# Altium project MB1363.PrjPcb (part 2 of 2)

## Sheet MCU_144_POWER.SchDoc: MCU 144 POWER
size A4; Date: Not used; ApprovedBy: Not used; CheckedBy: Not used; Author: Not used; CompanyName: STMicroelectronics; DrawnBy: Not used; Engineer: Not used; Organization: Not used; Address1: Not used; Address2: Not used; Address3: Not used; Address4: Not used; DocumentNumber: 4; Revision: Not used; SheetNumber: 4; SheetTotal: 9
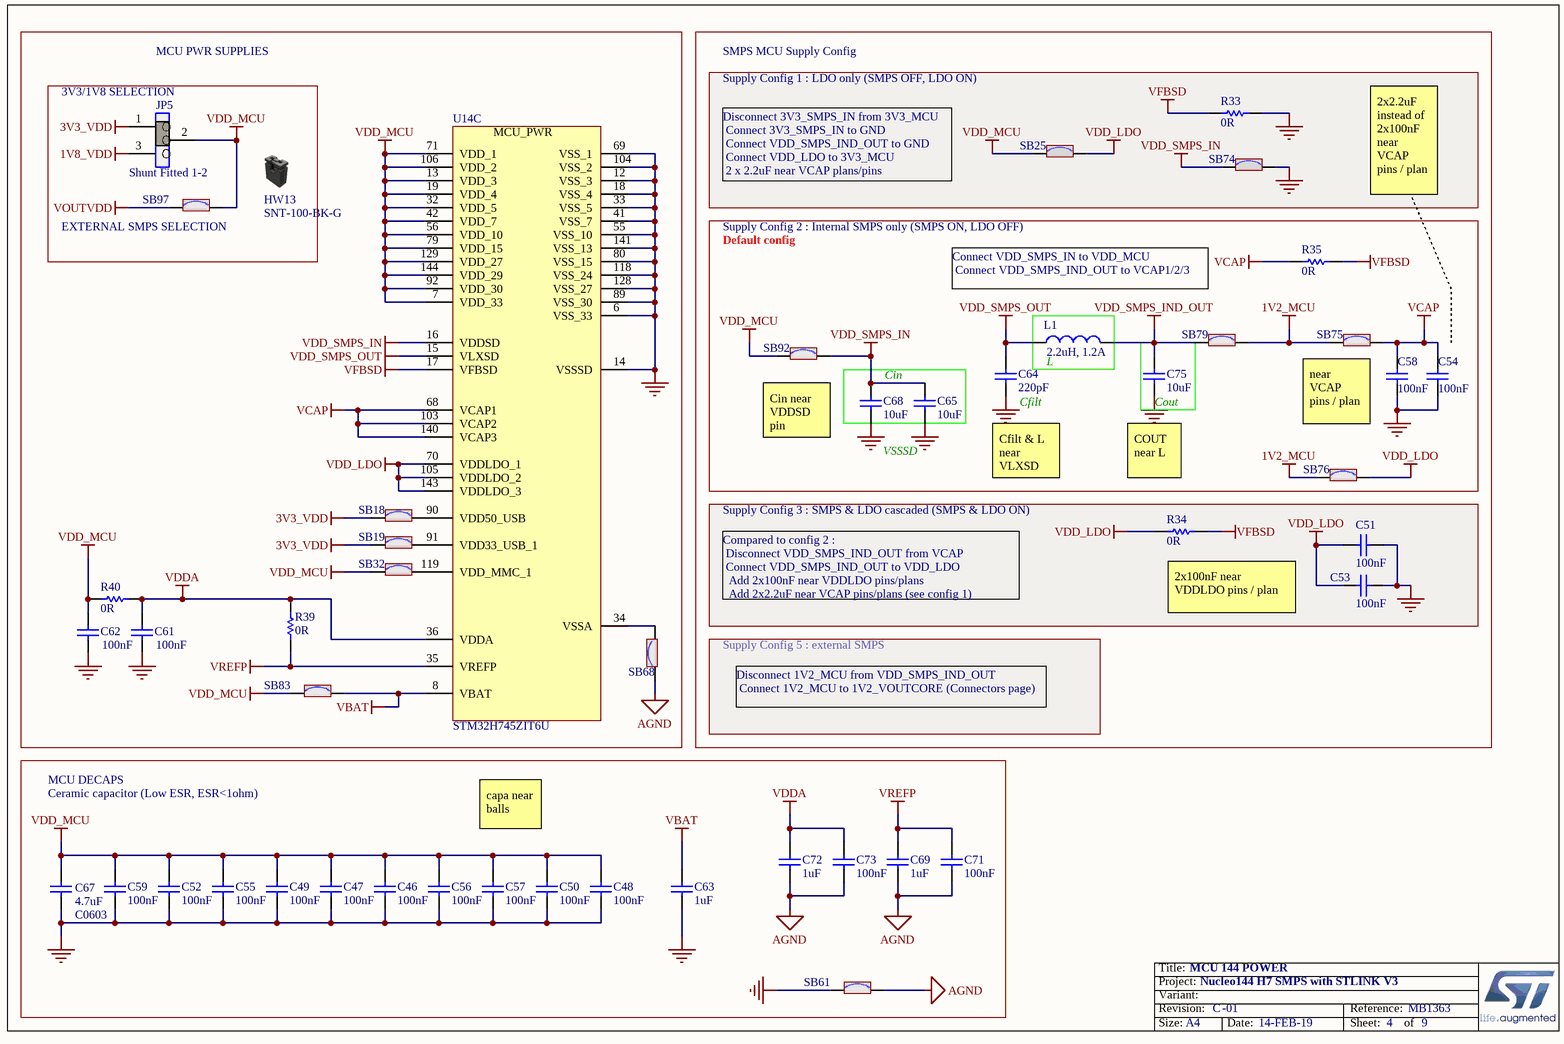
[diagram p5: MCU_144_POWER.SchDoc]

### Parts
C46  value 100nF  [C0402]  (hidden comment: Capacitor)
C47  value 100nF  [C0402]  (hidden comment: Capacitor)
C48  value 100nF  [C0402]  (hidden comment: Capacitor)
C49  value 100nF  [C0402]  (hidden comment: Capacitor)
C50  value 100nF  [C0402]  (hidden comment: Capacitor)
C51  value 100nF  [C0402]  (hidden comment: Capacitor)
C52  value 100nF  [C0402]  (hidden comment: Capacitor)
C53  value 100nF  [C0402]  (hidden comment: Capacitor)
C54  value 100nF  [C0402]  (hidden comment: Capacitor)
C55  value 100nF  [C0402]  (hidden comment: Capacitor)
C56  value 100nF  [C0402]  (hidden comment: Capacitor)
C57  value 100nF  [C0402]  (hidden comment: Capacitor)
C58  value 100nF  [C0402]  (hidden comment: Capacitor)
C59  value 100nF  [C0402]  (hidden comment: Capacitor)
C61  value 100nF  [C0402]  (hidden comment: Capacitor)
C62  value 100nF  [C0402]  (hidden comment: Capacitor)
C63  value 1uF  [C0603]  (hidden comment: Capacitor)
C64  value 220pF  [C0402]  (hidden comment: Capacitor)
C65  value 10uF  [C0402]  (hidden comment: Capacitor)
C67  value 4.7uF  [C0603]  (hidden comment: Capacitor)
C68  value 10uF  [C0402]  (hidden comment: Capacitor)
C69  value 1uF  [C0603]  (hidden comment: Capacitor)
C71  value 100nF  [C0402]  (hidden comment: Capacitor)
C72  value 1uF  [C0603]  (hidden comment: Capacitor)
C73  value 100nF  [C0402]  (hidden comment: Capacitor)
C75  value 10uF  [C0603]  (hidden comment: Capacitor)
HW13  value SNT-100-BK-G  (hidden comment: Shunt Black 2.54mm)  (mechanical)
JP5  value Shunt Fitted 1-2  [CON_SAMTEC_TSW-103-07-F-S]  (hidden comment: Jumper_Header 3x1 Fitted 1-2)
L1  value 2.2uH, 1.2A  [L0805_H0P9]  (hidden comment: Inductor)
R33  value 0R  [R0402]  (hidden comment: Resistor)
R34  value 0R  [R0402]  (hidden comment: Resistor)
R35  value 0R  [R0402]  (hidden comment: Resistor)
R39  value 0R  [R0603]  (hidden comment: Resistor)
R40  value 0R  [R0603]  (hidden comment: Resistor)
SB18  SB_ON  [SOLDER-BRIDGE_R0603-0R]  (value not drawn)
SB19  SB_ON  [SOLDER-BRIDGE_R0603-0R]  (value not drawn)
SB25  SB_ON  [SOLDER-BRIDGE_R0603-0R]  (value not drawn)
SB32  SB_ON  [SOLDER-BRIDGE_R0603-0R]  (value not drawn)
SB61  SB_ON  [SOLDER-BRIDGE_R0603-0R]  (value not drawn)
SB68  SB_ON  [SOLDER-BRIDGE_R0603-0R]  (value not drawn)
SB74  SB_ON  [SOLDER-BRIDGE_R0603-0R]  (value not drawn)
SB75  SB_ON  [SOLDER-BRIDGE_R0603-0R]  (value not drawn)
SB76  SB_ON  [SOLDER-BRIDGE_R0603-0R]  (value not drawn)
SB79  SB_ON  [SOLDER-BRIDGE_R0603-0R]  (value not drawn)
SB83  SB_ON  [SOLDER-BRIDGE_R0603-0R]  (value not drawn)
SB92  SB_ON  [SOLDER-BRIDGE_R0603-0R]  (value not drawn)
SB97  SB_ON  [SOLDER-BRIDGE_R0603-0R]  (value not drawn)
U14  value STM32H745ZIT6U  [ICC_LQFP144_20X20_P050_SOCKET_YAMAICHI_IC149-144-145-B5_NM]  (hidden comment: STM32H7_LQFP144_SMPS)  (part C of 3)

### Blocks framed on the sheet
L: L1
Cout: C75
Cin: C65 C68
Supply Config 3 : SMPS & LDO cascaded (SMPS & LDO ON): C51 C53 R34

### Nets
1V2_MCU: SB75.2 SB76.2 SB79.1
1V8_VDD: JP5.3
3V3_VDD: JP5.1 SB18.2 SB19.2
AGND: C69.2 C71.1 C72.2 C73.1 SB61.2 SB68.1
GND: C46.1 C47.1 C48.1 C49.1 C50.1 C51.2 C52.1 C53.2 C54.1 C55.1 C56.1 C57.1 C58.1 C59.1 C61.2 C62.2 C63.1 C64.1 C65.1 C67.1 C68.1 C75.1 R33.2 SB61.1 SB74.1 U14.6(VSS_33) U14.12(VSS_3) U14.14(VSSSD) U14.18(VSS_4) U14.33(VSS_5) U14.41(VSS_7) U14.55(VSS_10) U14.69(VSS_1) U14.80(VSS_15) U14.89(VSS_30) U14.104(VSS_2) U14.118(VSS_24) U14.128(VSS_27) U14.141(VSS_13)
VBAT: C63.2 SB83.2 U14.8(VBAT)
VCAP: C54.2 C58.2 R35.1 SB75.1 U14.68(VCAP1) U14.103(VCAP2) U14.140(VCAP3)
VDD_LDO: C51.1 C53.1 R34.1 SB25.1 SB76.1 U14.70(VDDLDO_1) U14.105(VDDLDO_2) U14.143(VDDLDO_3)
VDD_MCU: C46.2 C47.2 C48.2 C49.2 C50.2 C52.2 C55.2 C56.2 C57.2 C59.2 C62.1 C67.2 JP5.2 R40.1 SB25.2 SB32.2 SB83.1 SB92.2 SB97.2 U14.7(VDD_33) U14.13(VDD_3) U14.19(VDD_4) U14.32(VDD_5) U14.42(VDD_7) U14.56(VDD_10) U14.71(VDD_1) U14.79(VDD_15) U14.92(VDD_30) U14.106(VDD_2) U14.129(VDD_27) U14.144(VDD_29)
VDD_SMPS_IN: C65.2 C68.2 SB74.2 SB92.1 U14.16(VDDSD)
VDD_SMPS_IND_OUT: C75.2 L1.2 SB79.2
VDD_SMPS_OUT: C64.2 L1.1 U14.15(VLXSD)
VDDA: C61.1 C72.1 C73.2 R39.1 R40.2 U14.36(VDDA)
VFBSD: R33.1 R34.2 R35.2 U14.17(VFBSD)
VOUTVDD: SB97.1
VREFP: C69.1 C71.2 R39.2 U14.35(VREFP)
NetSB18_1: SB18.1 U14.90(VDD50_USB)
NetSB19_1: SB19.1 U14.91(VDD33_USB_1)
NetSB32_1: SB32.1 U14.119(VDD_MMC_1)
NetSB68_2: SB68.2 U14.34(VSSA)

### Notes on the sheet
- (near JP5) 3V3/1V8 SELECTION
- MCU PWR SUPPLIES
- SMPS MCU Supply Config
- Supply Config 1 : LDO only (SMPS OFF, LDO ON)
- Disconnect 3V3_SMPS_IN from 3V3_MCU
  Connect 3V3_SMPS_IN to GND
  Connect VDD_SMPS_IND_OUT to GND
  Connect VDD_LDO to 3V3_MCU
  2 x 2.2uF near VCAP plans/pins
- (near SB97) EXTERNAL SMPS SELECTION
- Default config
- Supply Config 2 : Internal SMPS only (SMPS ON, LDO OFF)
- 2x2.2uF instead of 2x100nF near VCAP pins / plan
- Connect VDD_SMPS_IN to VDD_MCU
  Connect VDD_SMPS_IND_OUT to VCAP1/2/3
- Cin near VDDSD pin
- (near C64) Cfilt
- near VCAP pins / plan
- VSSSD
- (near C64) Cfilt & L near VLXSD pin
- COUT near L
- Supply Config 5 : external SMPS
- Compared to config 2 :
  Disconnect VDD_SMPS_IND_OUT from VCAP
  Connect VDD_SMPS_IND_OUT to VDD_LDO
  Add 2x100nF near VDDLDO pins/plans
  Add 2x2.2uF near VCAP pins/plans (see config 1)
- (near R34) 2x100nF near VDDLDO pins / plan
- Disconnect 1V2_MCU from VDD_SMPS_IND_OUT
  Connect 1V2_MCU to 1V2_VOUTCORE (Connectors page)
- MCU DECAPS
- Ceramic capacitor (Low ESR, ESR<1ohm)
- capa near balls

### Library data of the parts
C46-C59 C61 C62 C71 C73 = MCD-00006: Capacitor, MLCC, 100nF, 16V, X7R, 10%, 0402, T=0.5mm; Manufacturer_Part_Number: CC0402KRX7R7BB104; Manufacturer: YAGEO; Alternate_Manufacturer_Part_Number: GCM155R71C104KA55D; Alternate_Manufacturer: MURATA; Provided_By: SUBCO; ECCN_US: EAR99; ECCN_EU: NEC
C63 C69 C72 = MCD-00238: Capacitor, MLCC, 1uF, 6V3, X5R, 10%, 0603, T=0,8mm; Manufacturer_Part_Number: CC0603KRX5R5BB105; Manufacturer: YAGEO; Provided_By: SUBCO; ECCN_US: EAR99; ECCN_EU: NEC
C64 = MCD-01225: Capacitor, MLCC, 220pF, 50V, NPO, 5%, 0402, T=0,5mm; Manufacturer_Part_Number: CC0402JRNPO9BN221; Manufacturer: YAGEO; Provided_By: SUBCO
C65 C68 = MCD-01716: Capacitor, MLCC, 10uF, 6V3, X5R, 20%, 0402, T=0.5mm; Manufacturer_Part_Number: CC0402MRX5R5BB106; Manufacturer: YAGEO; Provided_By: SUBCO
C67 = MCD-01121: Capacitor, MLCC, 4.7µF, 10V, X5R, 20%, 0603, T=0,8mm; Manufacturer_Part_Number: GRM188R61A475ME15; Manufacturer: MURATA; Provided_By: SUBCO; ECCN_US: EAR99; ECCN_EU: NEC
C75 = MCD-01341: Capacitor, MLCC, 10uF, 6V3, X5R, 20%, 0603, T=0,8mm; Manufacturer_Part_Number: GRM188R60J106ME47D; Manufacturer: MURATA; Provided_By: SUBCO; ECCN_US: EAR99; ECCN_EU: NEC
HW13 = MCD-00043: SHUNT 2.54mm BLACK; Manufacturer: SAMTEC; Part_Type: Mechanical; Alternate_Manufacturer_Part_Number: 316102S111A; Alternate_Manufacturer: JIUBABA; Provided_By: SUBCO
JP5 = MCD-00684: Header, 3x1, 2,54mm, VR, TH, Height 5.84mm/2.54mm - Shunt Fitted 1-2 by default; Part_Type: Connector; Manufacturer_Part_Number: TSW-103-07-F-S; Manufacturer: SAMTEC; Provided_By: SUBCO
L1 = MCD-01340: Inductor, 2.2uH, 20%, Isat 1.2A, DCR 0.228Ohm, 0805; Manufacturer_Part_Number: DFE201210U-2R2M=P2; Manufacturer: MURATA; Provided_By: SUBCO
R33-R35 = MCD-00052: Resistor,0R,0402,5%,1/16W; Manufacturer_Part_Number: RC0402JR-070RL; Manufacturer: YAGEO; Provided_By: SUBCO; ECCN_US: EAR99; ECCN_EU: NEC
R39 R40 = MCD-00056: Resistor,0R,0603,5%,1/10W; Manufacturer_Part_Number: RC0603JR-070RL; Manufacturer: YAGEO; Provided_By: SUBCO; ECCN_US: EAR99; ECCN_EU: NEC
SB18 SB19 SB25 SB32 SB61 SB68 SB74-SB76 SB79 SB83 SB92 SB97 = MCD-00071: Solder Bridge ON; Part_Type: Mechanical; Manufacturer_Part_Number: RC0603JR-070RL; Manufacturer: YAGEO; Provided_By: SUBCO
U14 = MCD-01401: STM32H745ZIT6U, LQFP144 package, 20x20, with socket footprint; Part_Type: IC; Manufacturer: STMICROELECTRONICS; BMS_Part_Number: 9175297 (cut 2.0); ECCN_US: 3A991A2; ECCN_EU: NEC; Provided_By: SUBCO with ST control

## Sheet USB.SchDoc: USB
size A4; Date: Not used; ApprovedBy: Not used; CheckedBy: Not used; Author: Not used; CompanyName: STMicroelectronics; DrawnBy: Not used; Engineer: Not used; Organization: Not used; Address1: Not used; Address2: Not used; Address3: Not used; Address4: Not used; DocumentNumber: 7; Revision: Not used; SheetNumber: 7; SheetTotal: 9
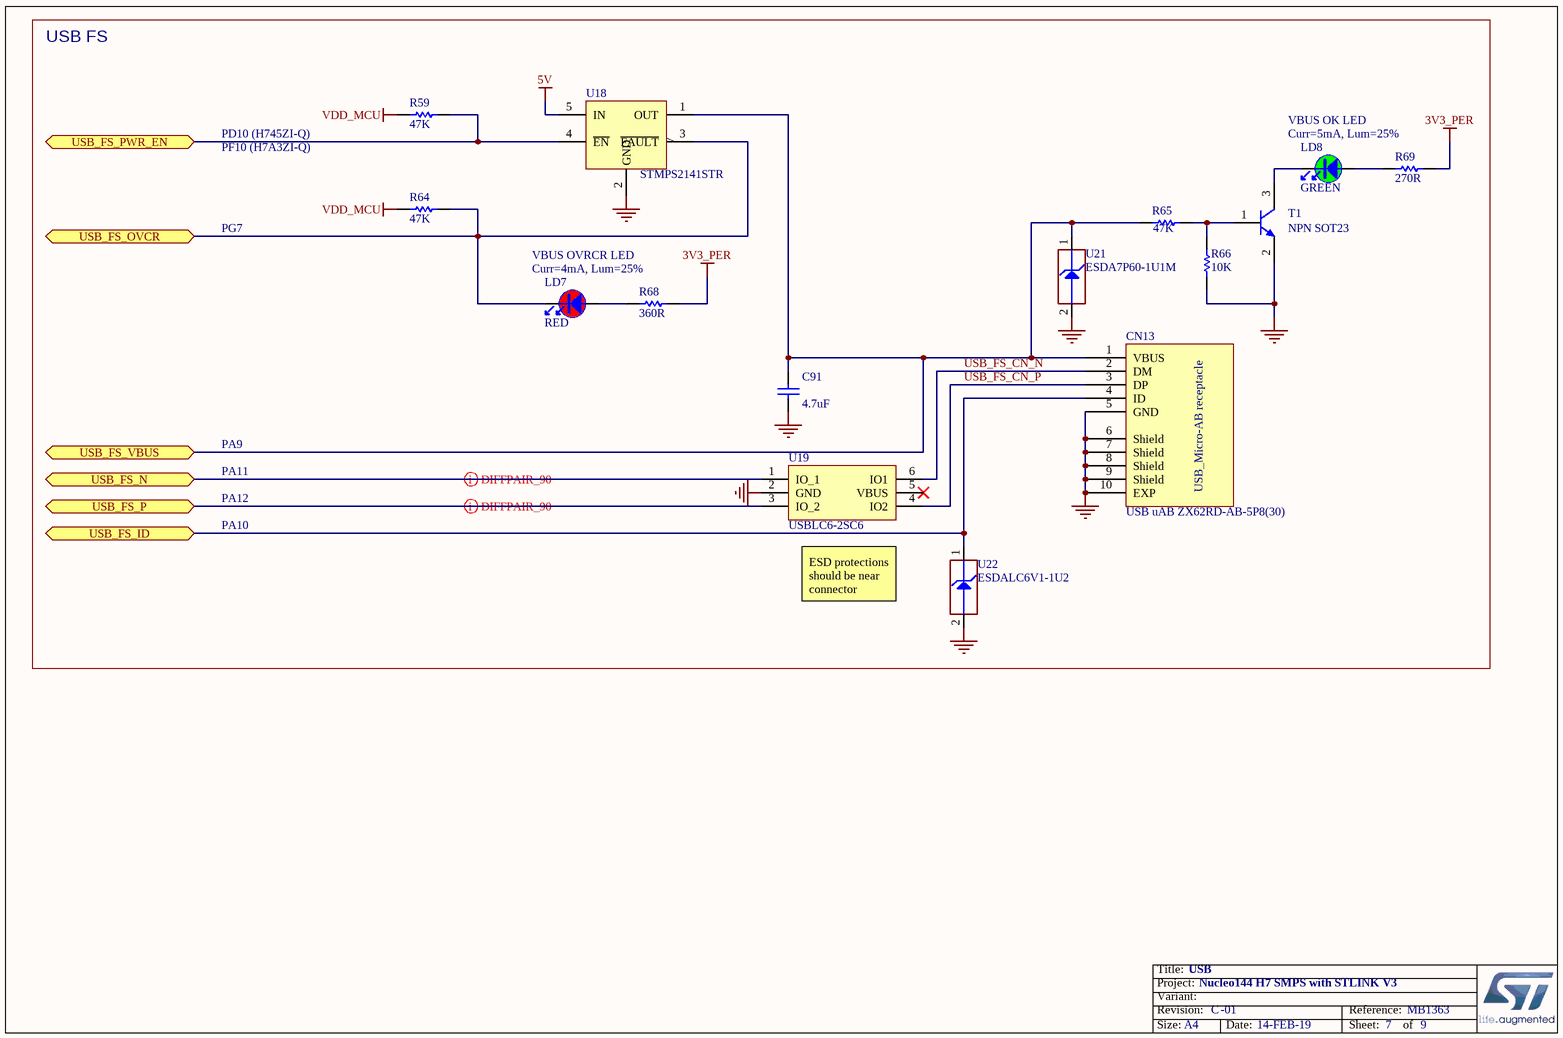
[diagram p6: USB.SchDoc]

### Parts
C91  value 4.7uF  [C0603]  (hidden comment: Capacitor)
CN13  value USB uAB ZX62RD-AB-5P8(30)  [CON_USBMICROAB_MOLEX_47590-0001_H3]  (hidden comment: USB_uAB_47590.0001)
LD7  value RED  [LED_0603_VISHAY_VLMS1300-GS08_RED_1A2K_H0P8]  (hidden comment: LED_red)
LD8  value GREEN  [LED_0603_OSRAM_LG-Q396-PS-35_GREEN_1A2K_H0P4]  (hidden comment: LED_green)
R59  value 47K  [R0402]  (hidden comment: Resistor)
R64  value 47K  [R0402]  (hidden comment: Resistor)
R65  value 47K  [R0402]  (hidden comment: Resistor)
R66  value 10K  [R0402]  (hidden comment: Resistor)
R68  value 360R  [R0402]  (hidden comment: Resistor)
R69  value 270R  [R0402]  (hidden comment: Resistor)
T1  value NPN SOT23  [NPN_SOT23]  (hidden comment: 9013-SOT23)
U18  STMPS2141STR  [MOS_SOT23-5L]
U19  USBLC6-2SC6  [ESD_SOT23-6L]
U21  value ESDA7P60-1U1M  [ESD_QFN2_1P6X1_P125]  (hidden comment: ESD-TRANSIL)
U22  value ESDALC6V1-1U2  [ESD_ST0201]  (hidden comment: ESD-TRANSIL)

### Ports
USB_FS_ID, USB_FS_N, USB_FS_OVCR, USB_FS_P, USB_FS_PWR_EN, USB_FS_VBUS

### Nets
3V3_PER: R68.2 R69.2
5V: U18.5(IN)
GND: C91.1 CN13.5(GND) CN13.6(Shield) CN13.7(Shield) CN13.8(Shield) CN13.9(Shield) CN13.10(EXP) R66.1 T1.2(E) U18.2(GND) U19.2(GND) U21.2(GND) U22.2(GND)
VDD_MCU: R59.2 R64.2
USB_FS_CN_N: CN13.2(DM) U19.6(IO1)
USB_FS_CN_P: CN13.3(DP) U19.4(IO2)
USB_FS_ID: CN13.4(ID) U22.1(IO1) ; port USB_FS_ID
USB_FS_N: U19.1(IO_1) ; port USB_FS_N
USB_FS_OVCR: LD7.2 R64.1 U18.3(~{FAULT}) ; port USB_FS_OVCR
USB_FS_P: U19.3(IO_2) ; port USB_FS_P
USB_FS_PWR_EN: R59.1 U18.4(~{EN}) ; port USB_FS_PWR_EN
USB_FS_VBUS: C91.2 CN13.1(VBUS) R65.1 U18.1(OUT) U21.1(IO1) ; port USB_FS_VBUS
NetLD7_1: LD7.1 R68.1
NetLD8_1: LD8.1 R69.1
NetLD8_2: LD8.2 T1.3(C)
NetR65_2: R65.2 R66.2 T1.1(B)

Not connected (* = marked no-connect by the designer): U19 5(VBUS)*

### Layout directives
differential pair: USB_FS_N, USB_FS_P

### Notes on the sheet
- USB FS
- PD10 (H745ZI-Q)
- PF10 (H7A3ZI-Q)
- VBUS OK LED
- Curr=5mA, Lum=25%
- PG7
- VBUS OVRCR LED
- Curr=4mA, Lum=25%
- PA9
- PA11
- PA12
- PA10
- (near U19) ESD protections should be near connector

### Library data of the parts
C91 = MCD-00009: Capacitor, MLCC, 4.7uF, 16V, X5R, 10%, 0603, T=0.8mm; Manufacturer_Part_Number: CC0603KRX5R7BB475; Manufacturer: YAGEO; Provided_By: SUBCO; ECCN_US: EAR99; ECCN_EU: NEC
CN13 = MCD-00661: USB-MICRO-AB Receptacle, RA, SMT + DIP, Standard, Top Mount, USB certified (symbol & footprint compatible with MCD-00022); Part_Type: Connector; Manufacturer_Part_Number: ZX62RD-AB-5P8(30); Manufacturer: HIROSE; Provided_By: SUBCO
LD7 = MCD-00587: LED Red, 0603 SMD, 2V Forward Voltage; Part_Type: Display; Manufacturer_Part_Number: VLMS1300-GS08; Manufacturer: VISHAY; Alternate_Manufacturer_Part_Number: LS Q976-NR-1; Alternate_Manufacturer: OSRAM OPTO SEMICONDUCTORS; Provided_By: SUBCO
LD8 = MCD-00588: LED Green, 0603 SMD, Forward Voltage Typ=2V, Max=2.5V; Part_Type: Display; Manufacturer_Part_Number: LG Q396-PS-35; Manufacturer: OSRAM OPTO SEMICONDUCTORS; Alternate_Manufacturer_Part_Number: VLMTG1300-GS08; Alternate_Manufacturer: VISHAY SEMICONDUCTOR OPTO DIVISION; Provided_By: SUBCO
R59 R64 R65 = MCD-00063: Resistor,47K,0402,1%,1/16W; Manufacturer_Part_Number: RC0402FR-0747KL; Manufacturer: YAGEO; Provided_By: SUBCO; ECCN_US: EAR99; ECCN_EU: NEC
R66 = MCD-00053: Resistor,10K,0402,1%,1/16W; Manufacturer_Part_Number: RC0402FR-0710KL; Manufacturer: YAGEO; Provided_By: SUBCO; ECCN_US: EAR99; ECCN_EU: NEC
R68 = MCD-00461: Resistor,360R,0402,1%,1/16W; Manufacturer_Part_Number: RC0402FR-07360RL; Manufacturer: YAGEO; Provided_By: SUBCO; ECCN_US: EAR99; ECCN_EU: NEC
R69 = MCD-00441: Resistor,270R,0402,1%,1/16W; Manufacturer_Part_Number: RC0402FR-07270RL; Manufacturer: YAGEO; Provided_By: SUBCO; ECCN_US: EAR99; ECCN_EU: NEC
T1 = MCD-00073: NPN Bipolar Transistor; Manufacturer_Part_Number: BSR14; Manufacturer: ON SEMICONDUCTOR; Part_Type: IC; Alternate_Manufacturer_Part_Number: MMBT2222LT1G / MMBT2222ALT1G / MMBT2222ALT3G; Provided_By: SUBCO; ECCN_US: EAR99; ECCN_EU: NEC
U18 = MCD-00083: Enhanced single channel power switches with active low enable pin; Part_Type: IC; Manufacturer: STMICROELECTRONICS; Alternate_Manufacturer_Part_Number: TPS2041C; Alternate_Manufacturer: TEXAS INSTRUMENTS; BMS_Part_Number: 9159003; Provided_By: SUBCO with ST control; ECCN_US: EAR99; ECCN_EU: NEC
U19 = MCD-00163: Very low capacitance ESD protection; Part_Type: IC; Manufacturer: STMICROELECTRONICS; BMS_Part_Number: 9151075; Provided_By: SUBCO with ST control; ECCN_US: EAR99; ECCN_EU: NEC
U21 = MCD-00251: High power transient voltage suppressor, 7V breakdown; Part_Type: Diode; Manufacturer: STMICROELECTRONICS; BMS_Part_Number: 9179042; Provided_By: SUBCO with ST control; ECCN_US: EAR99; ECCN_EU: NEC
U22 = MCD-00170: ESD protection 6V1; Part_Type: Diode; Manufacturer: STMICROELECTRONICS; BMS_Part_Number: 9151132; Provided_By: SUBCO with ST control; ECCN_US: EAR99; ECCN_EU: NEC

## Sheet Ethernet.SchDoc: Ethernet PHY with RJ45 connector
size A4; Date: Not used; ApprovedBy: Not used; CheckedBy: Not used; Author: Not used; CompanyName: STMicroelectronics; DrawnBy: Not used; Engineer: Not used; Organization: Not used; Address1: Not used; Address2: Not used; Address3: Not used; Address4: Not used; DocumentNumber: 6; Revision: Not used; SheetNumber: 6; SheetTotal: 9
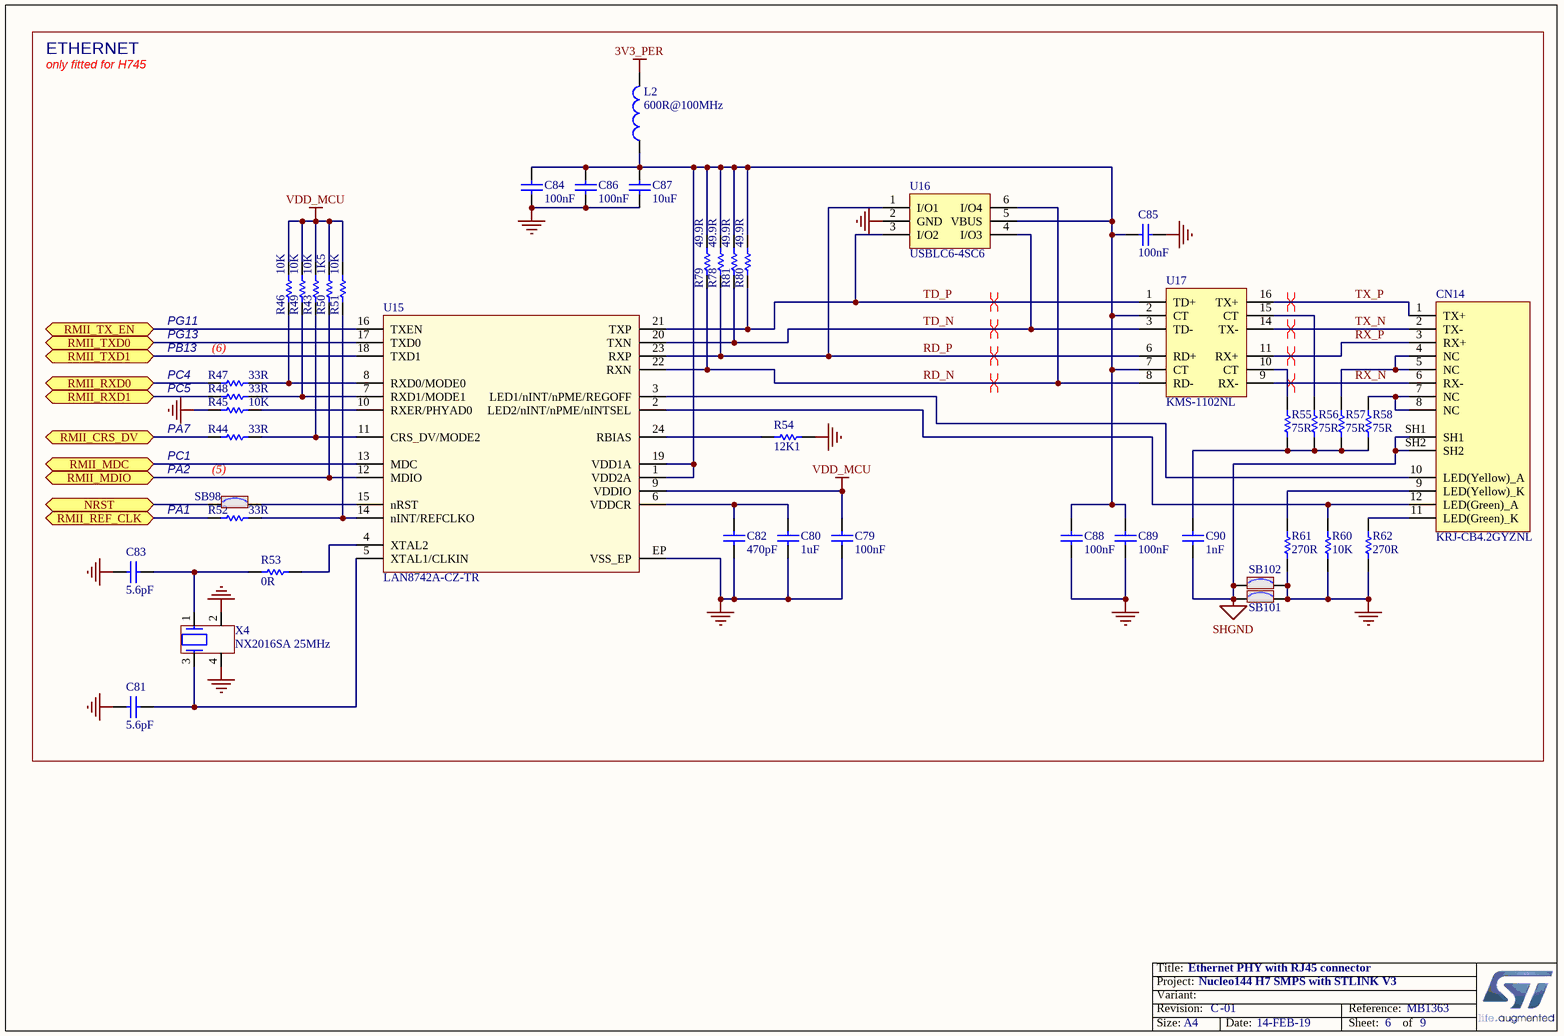
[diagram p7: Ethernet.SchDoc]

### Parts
C79  value 100nF  [C0603]  (hidden comment: Capacitor)
C80  value 1uF  [C0402]  (hidden comment: Capacitor)
C81  value 5.6pF  [C0402]  (hidden comment: Capacitor)
C82  value 470pF  [C0402]  (hidden comment: Capacitor)
C83  value 5.6pF  [C0402]  (hidden comment: Capacitor)
C84  value 100nF  [C0603]  (hidden comment: Capacitor)
C85  value 100nF  [C0603]  (hidden comment: Capacitor)
C86  value 100nF  [C0603]  (hidden comment: Capacitor)
C87  value 10uF  [C0603]  (hidden comment: Capacitor)
C88  value 100nF  [C0603]  (hidden comment: Capacitor)
C89  value 100nF  [C0603]  (hidden comment: Capacitor)
C90  value 1nF  [C1206_H1P6]  (hidden comment: Capacitor)
CN14  value KRJ-CB4.2GYZNL  [CON_RJ45_DGKYD_KRJ-CB4.2GYZNL]  (hidden comment: RJ45_KRJ-CB4.2GYZNL)
L2  value 600R@100MHz  [L0603]  (hidden comment: BEAD)
R43  value 10K  [R0402]  (hidden comment: Resistor)
R44  value 33R  [R0402]  (hidden comment: Resistor)
R45  value 10K  [R0402]  (hidden comment: Resistor)
R46  value 10K  [R0402]  (hidden comment: Resistor)
R47  value 33R  [R0402]  (hidden comment: Resistor)
R48  value 33R  [R0402]  (hidden comment: Resistor)
R49  value 10K  [R0402]  (hidden comment: Resistor)
R50  value 1K5  [R0402]  (hidden comment: Resistor)
R51  value 10K  [R0402]  (hidden comment: Resistor)
R52  value 33R  [R0402]  (hidden comment: Resistor)
R53  value 0R  [R0402]  (hidden comment: Resistor)
R54  value 12K1  [R0402]  (hidden comment: Resistor)
R55  value 75R  [R0402]  (hidden comment: Resistor)
R56  value 75R  [R0402]  (hidden comment: Resistor)
R57  value 75R  [R0402]  (hidden comment: Resistor)
R58  value 75R  [R0402]  (hidden comment: Resistor)
R60  value 10K  [R0402]  (hidden comment: Resistor)
R61  value 270R  [R0402]  (hidden comment: Resistor)
R62  value 270R  [R0402]  (hidden comment: Resistor)
R78  value 49.9R  [R0402]  (hidden comment: Resistor)
R79  value 49.9R  [R0402]  (hidden comment: Resistor)
R80  value 49.9R  [R0402]  (hidden comment: Resistor)
R81  value 49.9R  [R0402]  (hidden comment: Resistor)
SB98  SB_ON  [SOLDER-BRIDGE_R0603-0R]  (value not drawn)
SB101  SB_ON  [SOLDER-BRIDGE_R0603-0R]  (value not drawn)
SB102  SB_ON  [SOLDER-BRIDGE_R0603-0R]  (value not drawn)
U15  LAN8742A-CZ-TR  [ICC_VQFN24-EPAD_4X4_P050]
U16  USBLC6-4SC6  [ESD_SOT23-6L]
U17  KMS-1102NL  [TRS_DGKYD_KMS-1102NL]
X4  value NX2016SA 25MHz  [CRY_NX2016SA_4P]  (hidden comment: XTAL_4_PINS)

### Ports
NRST (bidir), RMII_CRS_DV (bidir), RMII_MDC (bidir), RMII_MDIO (bidir), RMII_REF_CLK (bidir), RMII_RXD0 (bidir), RMII_RXD1 (bidir), RMII_TX_EN (bidir), RMII_TXD0 (bidir), RMII_TXD1 (bidir)

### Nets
3V3_PER: L2.2
GND: C79.1 C80.1 C81.1 C82.1 C83.1 C84.1 C85.2 C86.1 C87.1 C88.1 C89.1 R45.2 R54.2 R60.1 R61.1 R62.1 SB101.2 SB102.2 U15.EP(VSS_EP) U16.2(GND) X4.2 X4.4
SHGND: C90.1 CN14.SH1 CN14.SH2 SB101.1 SB102.1
VDD_MCU: C79.2 R43.2 R46.2 R49.2 R50.2 R51.2 U15.9(VDDIO)
NRST: SB98.1 ; port NRST
RD_N: R79.1 U15.22(RXN) U16.6(I/O4) U17.8(RD-)
RD_P: R78.1 U15.23(RXP) U16.1(I/O1) U17.6(RD+)
RMII_CRS_DV: R44.1 ; port RMII_CRS_DV
RMII_MDC: U15.13(MDC) ; port RMII_MDC
RMII_MDIO: R50.1 U15.12(MDIO) ; port RMII_MDIO
RMII_REF_CLK: R52.1 ; port RMII_REF_CLK
RMII_RXD0: R47.1 ; port RMII_RXD0
RMII_RXD1: R48.1 ; port RMII_RXD1
RMII_TX_EN: U15.16(TXEN) ; port RMII_TX_EN
RMII_TXD0: U15.17(TXD0) ; port RMII_TXD0
RMII_TXD1: U15.18(TXD1) ; port RMII_TXD1
RX_N: CN14.6(RX-) U17.9(RX-)
RX_P: CN14.3(RX+) U17.11(RX+)
TD_N: R81.1 U15.20(TXN) U16.4(I/O3) U17.3(TD-)
TD_P: R80.1 U15.21(TXP) U16.3(I/O2) U17.1(TD+)
TX_N: CN14.2(TX-) U17.14(TX-)
TX_P: CN14.1(TX+) U17.16(TX+)
NetC80_2: C80.2 C82.2 U15.6(VDDCR)
NetC81_2: C81.2 U15.5(XTAL1/CLKIN) X4.3
NetC83_2: C83.2 R53.1 X4.1
NetC84_2: C84.2 C85.1 C86.2 C87.2 C88.2 C89.2 L2.1 R78.2 R79.2 R80.2 R81.2 U15.1(VDD2A) U15.19(VDD1A) U16.5(VBUS) U17.2(CT) U17.7(CT)
NetC90_2: C90.2 R55.1 R56.1 R57.1 R58.1
NetCN14_4: CN14.4(NC) CN14.5(NC) R57.2
NetCN14_7: CN14.7(NC) CN14.8(NC) R58.2
NetCN14_9: CN14.9(LED(Yellow)_K) R61.2
NetCN14_10: CN14.10(LED(Yellow)_A) U15.3(LED1/nINT/nPME/REGOFF)
NetCN14_11: CN14.11(LED(Green)_K) R62.2
NetCN14_12: CN14.12(LED(Green)_A) R60.2 U15.2(LED2/nINT/nPME/nINTSEL)
NetR43_1: R43.1 R44.2 U15.11(CRS_DV/MODE2)
NetR45_1: R45.1 U15.10(RXER/PHYAD0)
NetR46_1: R46.1 R47.2 U15.8(RXD0/MODE0)
NetR48_2: R48.2 R49.1 U15.7(RXD1/MODE1)
NetR51_1: R51.1 R52.2 U15.14(nINT/REFCLKO)
NetR53_2: R53.2 U15.4(XTAL2)
NetR54_1: R54.1 U15.24(RBIAS)
NetR55_2: R55.2 U17.10(CT)
NetR56_2: R56.2 U17.15(CT)
NetSB98_2: SB98.2 U15.15(nRST)

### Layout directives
differential pair: RD_N, RD_P, RX_N, RX_P, TD_N, TD_P, TX_N, TX_P

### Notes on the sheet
- ETHERNET
- only fitted for H745
- PG11
- PG13
- PB13
- PC4
- (6)
- PC5
- PA7
- PC1
- PA2
- PA1
- (5)

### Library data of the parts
C79 C84-C86 C88 C89 = MCD-00237: Capacitor, MLCC, 100nF, 6V3, X5R, 10%, 0603, T=0,8mm; Manufacturer_Part_Number: CC0603KRX5R5BB104; Manufacturer: YAGEO; Provided_By: SUBCO; ECCN_US: EAR99; ECCN_EU: NEC
C80 = MCD-00095: Capacitor, MLCC, 1uF, 6V3, X5R, 10%, 0402, T=0,5mm; Manufacturer_Part_Number: GRM155R61E105KA12; Manufacturer: MURATA; Alternate_Manufacturer_Part_Number: GRM155R60J105KE19; Provided_By: SUBCO; ECCN_US: EAR99; ECCN_EU: NEC
C81 C83 = MCD-01374: Capacitor, MLCC, 5.6pF, 50V, NPO, 5%, 0402, T=0,5mm; Manufacturer_Part_Number: CC0402BRNPO9BN5R6; Manufacturer: YAGEO; Provided_By: SUBCO
C82 = MCD-00724: Capacitor, MLCC, 470pF, 50V, NPO, 5%, 0402, T=0,5mm; Manufacturer_Part_Number: CC0402JRNPO9BN471; Manufacturer: YAGEO; Provided_By: SUBCO
C87 = MCD-01124: Capacitor, MLCC, 10µF, 10V, X5R, 10%, 0603, T=0.8mm; Manufacturer_Part_Number: GRM188R61A106KAAL; Manufacturer: MURATA; Provided_By: SUBCO; ECCN_US: EAR99; ECCN_EU: NEC
C90 = MCD-00722: Capacitor, MLCC, 1nF, 2KV, X7R, 10%, 1206, T=1,25mm; Manufacturer_Part_Number: CC1206KKX7RDBB102; Manufacturer: YAGEO; Provided_By: SUBCO
CN14 = MCD-00717: RJ45 jack, single port, with LEDS, Metal shielded dip low profile; Part_Type: Connector; Manufacturer: DONGGUAN KEYOUDA ELECTRONIC TECHNOLOGY; Provided_By: SUBCO
L2 = MCD-00047: SMD Chip ferrite bead, 600R@100MHz +/-25%, 350mA, 500mohm DC, 0603, T=0.8mm; Part_Type: Inductor; Manufacturer_Part_Number: FCM1608KF-601T03; Manufacturer: TAI-TECH; Provided_By: SUBCO
R43 R45 R46 R49 R51 R60 = MCD-00053: as R66 on sheet USB
R44 R47 R48 R52 = MCD-00455: Resistor,33R,0402,1%,1/16W; Manufacturer_Part_Number: RC0402FR-0733RL; Manufacturer: YAGEO; Provided_By: SUBCO; ECCN_US: EAR99; ECCN_EU: NEC
R50 = MCD-00068: Resistor,1K5,0402,1%,1/16W; Manufacturer_Part_Number: RC0402FR-071K5L; Manufacturer: YAGEO; Provided_By: SUBCO; ECCN_US: EAR99; ECCN_EU: NEC
R53 = MCD-00052: as R33 on sheet MCU_144_POWER
R54 = MCD-00723: Resistor,12K1,0402,1%,1/16W; Manufacturer_Part_Number: RC0402FR-0712K1L; Manufacturer: YAGEO; Provided_By: SUBCO; ECCN_US: EAR99; ECCN_EU: NEC
R55-R58 = MCD-00515: Resistor,75R,0402,1%,1/16W; Manufacturer_Part_Number: RC0402FR-0775RL; Manufacturer: YAGEO; Provided_By: SUBCO; ECCN_US: EAR99; ECCN_EU: NEC
R61 R62 = MCD-00441: as R69 on sheet USB
R78-R81 = MCD-00565: Resistor,49R9,0402,1%,1/16W; Manufacturer_Part_Number: RC0402FR-0749R9L; Manufacturer: YAGEO; Provided_By: SUBCO; ECCN_US: EAR99; ECCN_EU: NEC
SB98 SB101 SB102 = MCD-00071: as SB18 on sheet MCU_144_POWER
U15 = MCD-00719: 10/100M RMII Ethernet transceiver; Part_Type: IC; Manufacturer: MICROCHIP; Provided_By: SUBCO
U16 = MCD-00250: Very low capacitance ESD protection , 4 lines; Part_Type: IC; Manufacturer: STMICROELECTRONICS; BMS_Part_Number: 9151001; Provided_By: SUBCO with ST control; ECCN_US: EAR99; ECCN_EU: NEC
U17 = MCD-00718: Discrete Magnetic Transformer Module, 16 pins, SMT, 100 Base-TX; Part_Type: IC; Manufacturer: DONGGUAN KEYOUDA ELECTRONIC TECHNOLOGY; Provided_By: SUBCO
X4 = MCD-01364: Crystal 25MHz, 6pF, +-20ppm, 80ohms max, SMD; Part_Type: Crystal_Osc; Manufacturer_Part_Number: NX2016SA 25MHz EXS00A-CS11321; Manufacturer: NDK; BMS_Part_Number: 9157044; Provided_By: SUBCO; ECCN_US: EAR99; ECCN_EU: NEC

## Sheet ST_LINK_V3E.SchDoc: STLINK_V3E
size A3; Date: Not used; ApprovedBy: Not used; CheckedBy: Not used; Author: Not used; CompanyName: STMicroelectronics; DrawnBy: Not used; Engineer: Not used; Organization: Not used; Address1: Not used; Address2: Not used; Address3: Not used; Address4: Not used; DocumentNumber: 10; Revision: Not used; SheetNumber: 9; SheetTotal: 9
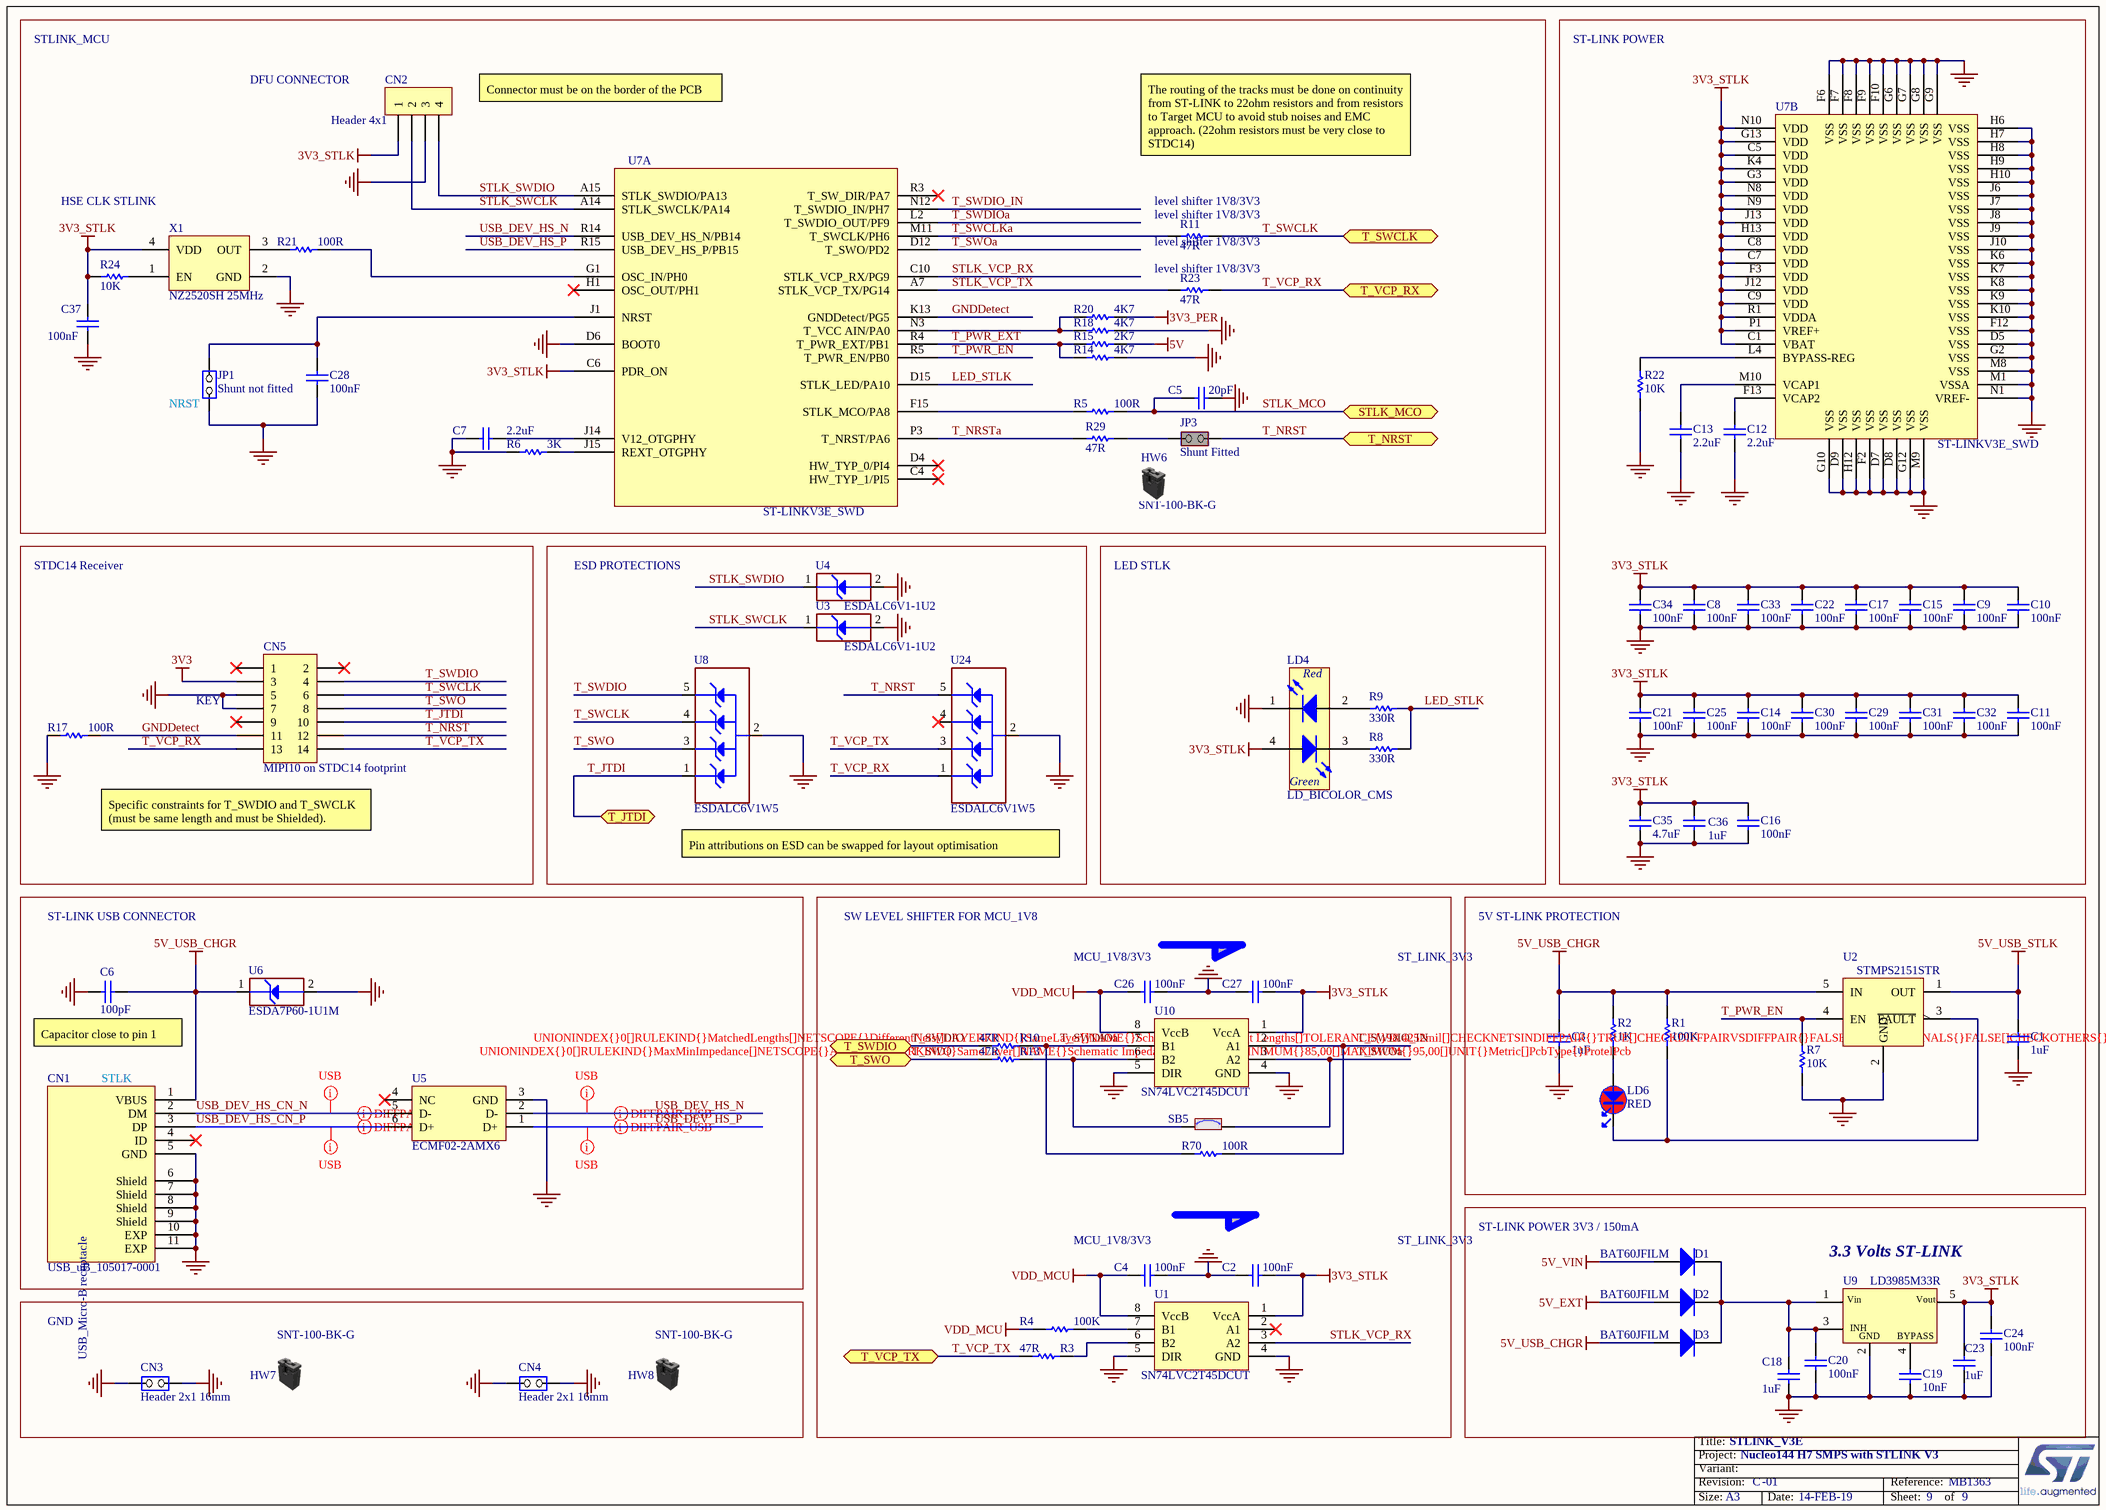
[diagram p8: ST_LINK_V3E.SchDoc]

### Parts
C1  value 1uF  [C0603]  (hidden comment: Capacitor)
C2  value 100nF  [C0603]  (hidden comment: Capacitor)
C3  value 1uF  [C0603]  (hidden comment: Capacitor)
C4  value 100nF  [C0603]  (hidden comment: Capacitor)
C5  value 20pF  [C0402]  (hidden comment: Capacitor)
C6  value 100pF  [C0402]  (hidden comment: Capacitor)
C7  value 2.2uF  [C0603]  (hidden comment: Capacitor)
C8  value 100nF  [C0402]  (hidden comment: Capacitor)
C9  value 100nF  [C0402]  (hidden comment: Capacitor)
C10  value 100nF  [C0402]  (hidden comment: Capacitor)
C11  value 100nF  [C0402]  (hidden comment: Capacitor)
C12  value 2.2uF  [C0603]  (hidden comment: Capacitor)
C13  value 2.2uF  [C0603]  (hidden comment: Capacitor)
C14  value 100nF  [C0402]  (hidden comment: Capacitor)
C15  value 100nF  [C0402]  (hidden comment: Capacitor)
C16  value 100nF  [C0402]  (hidden comment: Capacitor)
C17  value 100nF  [C0402]  (hidden comment: Capacitor)
C18  value 1uF  [C0603]  (hidden comment: Capacitor)
C19  value 10nF  [C0402]  (hidden comment: Capacitor)
C20  value 100nF  [C0402]  (hidden comment: Capacitor)
C21  value 100nF  [C0402]  (hidden comment: Capacitor)
C22  value 100nF  [C0402]  (hidden comment: Capacitor)
C23  value 1uF  [C0603]  (hidden comment: Capacitor)
C24  value 100nF  [C0402]  (hidden comment: Capacitor)
C25  value 100nF  [C0402]  (hidden comment: Capacitor)
C26  value 100nF  [C0603]  (hidden comment: Capacitor)
C27  value 100nF  [C0603]  (hidden comment: Capacitor)
C28  value 100nF  [C0402]  (hidden comment: Capacitor)
C29  value 100nF  [C0402]  (hidden comment: Capacitor)
C30  value 100nF  [C0402]  (hidden comment: Capacitor)
C31  value 100nF  [C0402]  (hidden comment: Capacitor)
C32  value 100nF  [C0402]  (hidden comment: Capacitor)
C33  value 100nF  [C0402]  (hidden comment: Capacitor)
C34  value 100nF  [C0402]  (hidden comment: Capacitor)
C35  value 4.7uF  [C0603]  (hidden comment: Capacitor)
C36  value 1uF  [C0603]  (hidden comment: Capacitor)
C37  value 100nF  [C0402]  (hidden comment: Capacitor)
CN1  value USB_uB_105017-0001  [CON_USBMICROB_MOLEX_105017-0001_H2P90]  (hidden comment: USB_uB_105017.0001)
CN2  Header 4x1  [CON_SAMTEC_TSW-104-07-G-S]
CN3  value Header 2x1 16mm  [CON_SAMTEC_TSW-102-09-X-S]  (hidden comment: Jumper_Header 2x1)
CN4  value Header 2x1 16mm  [CON_SAMTEC_TSW-102-09-X-S]  (hidden comment: Jumper_Header 2x1)
CN5  value MIPI10 on STDC14 footprint  [CON_STDC14_Receiver_MEDIUM_WITH_MIPI10_3D]  (hidden comment: Header 7x2)
D1  BAT60JFILM  [DIO_SOD323]
D2  BAT60JFILM  [DIO_SOD323]
D3  BAT60JFILM  [DIO_SOD323]
HW6  value SNT-100-BK-G  (hidden comment: Shunt Black 2.54mm)  (mechanical)
HW7  value SNT-100-BK-G  (hidden comment: Shunt Black 2.54mm)  (mechanical)
HW8  value SNT-100-BK-G  (hidden comment: Shunt Black 2.54mm)  (mechanical)
JP1  value Shunt not fitted  [CON_SAMTEC_TSW-102-07-G-S]  (hidden comment: Jumper_Header 2x1)
JP3  value Shunt Fitted  [CON_SAMTEC_TSW-102-07-G-S]  (hidden comment: Jumper_Header 2x1 Fitted)
LD4  LD_BICOLOR_CMS  [LED_BI-GR_HSMF-A201-A00J1]
LD6  value RED  [LED_0603_RED]  (hidden comment: LED_red)
R1  value 100K  [R0603]  (hidden comment: Resistor)
R2  value 1K  [R0603]  (hidden comment: Resistor)
R3  value 47R  [R0402]  (hidden comment: Resistor)
R4  value 100K  [R0603]  (hidden comment: Resistor)
R5  value 100R  [R0402]  (hidden comment: Resistor)
R6  value 3K  [R0402]  (hidden comment: Resistor)
R7  value 10K  [R0603]  (hidden comment: Resistor)
R8  value 330R  [R0603]  (hidden comment: Resistor)
R9  value 330R  [R0603]  (hidden comment: Resistor)
R10  value 47R  [R0402]  (hidden comment: Resistor)
R11  value 47R  [R0402]  (hidden comment: Resistor)
R13  value 47R  [R0402]  (hidden comment: Resistor)
R14  value 4K7  [R0402]  (hidden comment: Resistor)
R15  value 2K7  [R0402]  (hidden comment: Resistor)
R17  value 100R  [R0402]  (hidden comment: Resistor)
R18  value 4K7  [R0402]  (hidden comment: Resistor)
R20  value 4K7  [R0402]  (hidden comment: Resistor)
R21  value 100R  [R0402]  (hidden comment: Resistor)
R22  value 10K  [R0402]  (hidden comment: Resistor)
R23  value 47R  [R0402]  (hidden comment: Resistor)
R24  value 10K  [R0402]  (hidden comment: Resistor)
R29  value 47R  [R0402]  (hidden comment: Resistor)
R70  value 100R  [R0402]  (hidden comment: Resistor)
SB5  SB_ON  [SOLDER-BRIDGE_R0603-0R]  (value not drawn)
U1  SN74LVC2T45DCUT  [ICC_VSSOP8_DCU_R-PDSO-G8_2X2P30_P050]
U2  STMPS2151STR  [MOS_SOT23-5L]
U3  value ESDALC6V1-1U2  [ESD_ST0201]  (hidden comment: ESD-TRANSIL)
U4  value ESDALC6V1-1U2  [ESD_ST0201]  (hidden comment: ESD-TRANSIL)
U5  ECMF02-2AMX6  [ESD_QFN-6L_1P7X1P5_P050]
U6  value ESDA7P60-1U1M  [ESD_QFN2_1P6X1_P125]  (hidden comment: ESD-TRANSIL)
U7  ST-LINKV3E_SWD  [ICC_UFBGA201_176+25_10X10_P065]  (parts A,B of 2)
U8  ESDALC6V1W5  [ESD_SOT323-5L]
U9  LD3985M33R  [REG_SOT23-5L]
U10  SN74LVC2T45DCUT  [ICC_VSSOP8_DCU_R-PDSO-G8_2X2P30_P050]
U24  ESDALC6V1W5  [ESD_SOT323-5L]
X1  value NZ2520SH 25MHz  [OSC_NDK_NZ2520SB_4P]  (hidden comment: OSCILLATOR_4_PINS)

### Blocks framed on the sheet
ST-LINK POWER: C8-C17 C21 C22 C25 C29-C36 R22 U7
ESD PROTECTIONS: U3 U4 U8 U24
LED STLK: LD4 R8 R9
5V ST-LINK PROTECTION: C1 C3 LD6 R1 R2 R7 U2
3.3 Volts ST-LINK: C18-C20 C23 C24 D1-D3 U9
GND: CN3 CN4 HW7 HW8

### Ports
STLK_MCO, T_JTDI (bidir), T_NRST, T_SWCLK, T_SWDIO, T_SWO, T_VCP_RX, T_VCP_TX

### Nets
3V3: CN5.3
3V3_PER: R20.2
3V3_STLK: C2.2 C8.2 C9.2 C10.2 C11.2 C14.2 C15.2 C16.2 C17.2 C21.2 C22.2 C23.2 C24.2 C25.2 C27.2 C29.2 C30.2 C31.2 C32.2 C33.2 C34.2 C35.2 C36.2 C37.2 CN2.1 LD4.4(YellowGreen_anode) R24.1 U1.1(VccA) U7.C1(VBAT) U7.C5(VDD) U7.C6(PDR_ON) U7.C7(VDD) U7.C8(VDD) U7.C9(VDD) U7.F3(VDD) U7.G3(VDD) U7.G13(VDD) U7.H13(VDD) U7.J12(VDD) U7.J13(VDD) U7.K4(VDD) U7.N8(VDD) U7.N9(VDD) U7.N10(VDD) U7.P1(VREF+) U7.R1(VDDA) U9.5(Vout) U10.1(VccA) X1.4(VDD)
5V: R15.1
5V_EXT: D2.1(A)
5V_USB_CHGR: C3.2 C6.2 CN1.1(VBUS) D3.1(A) R1.2 R2.2 U2.5(IN) U6.1(IO1)
5V_USB_STLK: C1.2 U2.1(OUT)
5V_VIN: D1.1(A)
GND: C1.1 C2.1 C3.1 C4.2 C5.1 C6.1 C7.1 C8.1 C9.1 C10.1 C11.1 C12.1 C13.1 C14.1 C15.1 C16.1 C17.1 C18.2 C19.1 C20.1 C21.1 C22.1 C23.1 C24.1 C25.1 C26.2 C27.1 C28.1 C29.1 C30.1 C31.1 C32.1 C33.1 C34.1 C35.1 C36.1 C37.1 CN1.5(GND) CN1.6(Shield) CN1.7(Shield) CN1.8(Shield) CN1.9(Shield) CN1.10(EXP) CN1.11(EXP) CN2.3 CN3.1(COMMON) CN3.2(NO) CN4.1(COMMON) CN4.2(NO) CN5.5 CN5.7 JP1.1(COMMON) LD4.1(RED_cathode) R6.1 R7.2 R14.1 R17.1 R18.2 R22.1 U1.4(GND) U1.5(DIR) U2.2(GND) U3.2(GND) U4.2(GND) U5.3(GND) U6.2(GND) U7.D5(VSS) U7.D6(BOOT0) U7.D7(VSS) U7.D8(VSS) U7.D9(VSS) U7.F2(VSS) U7.F6(VSS) U7.F7(VSS) U7.F8(VSS) U7.F9(VSS) U7.F10(VSS) U7.F12(VSS) U7.G2(VSS) U7.G6(VSS) U7.G7(VSS) U7.G8(VSS) U7.G9(VSS) U7.G10(VSS) U7.G12(VSS) U7.H6(VSS) U7.H7(VSS) U7.H8(VSS) U7.H9(VSS) U7.H10(VSS) U7.H12(VSS) U7.J6(VSS) U7.J7(VSS) U7.J8(VSS) U7.J9(VSS) U7.J10(VSS) U7.K6(VSS) U7.K7(VSS) U7.K8(VSS) U7.K9(VSS) U7.K10(VSS) U7.M1(VSSA) U7.M8(VSS) U7.M9(VSS) U7.N1(VREF-) U8.2(GND) U9.2(GND) U10.4(GND) U10.5(DIR) U24.2(GND) X1.2(GND)
VDD_MCU: C4.1 C26.1 R4.2 U1.8(VccB) U10.8(VccB)
GNDDetect: CN5.11 R17.2 U7.K13(GNDDetect/PG5)
LED_STLK: R8.2 R9.2 U7.D15(STLK_LED/PA10)
STLK_MCO: C5.2 R5.2 ; port STLK_MCO
STLK_SWCLK: CN2.2 U3.1(IO1) U7.A14(STLK_SWCLK/PA14)
STLK_SWDIO: CN2.4 U4.1(IO1) U7.A15(STLK_SWDIO/PA13)
STLK_VCP_RX: U1.3(A2) U7.C10(STLK_VCP_RX/PG9)
STLK_VCP_TX: R23.1 U7.A7(STLK_VCP_TX/PG14)
T_JTDI: CN5.10 U8.1(IO1) ; port T_JTDI  [project net PA15]
T_NRST: CN5.12 JP3.2(NO) U24.5(IO4) ; port T_NRST
T_NRSTa: R29.1 U7.P3(T_NRST/PA6)
T_PWR_EN: R7.1 U2.4(EN) U7.R5(T_PWR_EN/PB0)
T_PWR_EXT: R14.2 R15.2 U7.R4(T_PWR_EXT/PB1)
T_SWCLK: CN5.6 R11.2 U8.4(IO3) ; port T_SWCLK
T_SWCLKa: R11.1 U7.M11(T_SWCLK/PH6)
T_SWDIO: CN5.4 R10.1 U8.5(IO4) ; port T_SWDIO
T_SWDIO_IN: R70.2 U7.N12(T_SWDIO_IN/PH7) U10.2(A1)
T_SWDIOa: R10.2 R70.1 U7.L2(T_SWDIO_OUT/PF9) U10.7(B1)
T_SWO: CN5.8 R13.1 U8.3(IO2) ; port T_SWO
T_SWOa: SB5.1 U7.D12(T_SWO/PD2) U10.3(A2)
T_VCP_RX: CN5.13 R23.2 U24.1(IO1) ; port T_VCP_RX
T_VCP_TX: CN5.14 R3.1 U24.3(IO2) ; port T_VCP_TX
USB_DEV_HS_CN_N: CN1.2(DM) U5.5(D-)
USB_DEV_HS_CN_P: CN1.3(DP) U5.6(D+)
USB_DEV_HS_N: U5.2(D-) U7.R14(USB_DEV_HS_N/PB14)
USB_DEV_HS_P: U5.1(D+) U7.R15(USB_DEV_HS_P/PB15)
NetC7_2: C7.2 U7.J14(V12_OTGPHY)
NetC12_2: C12.2 U7.F13(VCAP2)
NetC13_2: C13.2 U7.M10(VCAP1)
NetC18_1: C18.1 C20.2 D1.2(K) D2.2(K) D3.2(K) U9.1(Vin) U9.3(CE)
NetC19_2: C19.2 U9.4(BYPASS)
NetC28_2: C28.2 JP1.2(NO) U7.J1(NRST)
NetJP3_1: JP3.1(COMMON) R29.2
NetLD4_2: LD4.2(Red_anode) R9.1
NetLD4_3: LD4.3(YellowGreen_cathode) R8.1
NetLD6_1: LD6.1 R2.1
NetLD6_2: LD6.2 R1.1 U2.3(~{FAULT})
NetR3_2: R3.2 U1.6(B2)
NetR4_1: R4.1 U1.7(B1)
NetR5_1: R5.1 U7.F15(STLK_MCO/PA8)
NetR6_2: R6.2 U7.J15(REXT_OTGPHY)
NetR13_2: R13.2 SB5.2 U10.6(B2)
NetR18_1: R18.1 R20.1 U7.N3(T_VCC_AIN/PA0)
NetR21_1: R21.1 X1.3(OUT)
NetR21_2: R21.2 U7.G1(OSC_IN/PH0)
NetR22_2: R22.2 U7.L4(BYPASS-REG)
NetR24_2: R24.2 X1.1(EN)

Not connected (* = marked no-connect by the designer): CN1 4(ID)*; CN5 1* 2* 9*; U1 2(A1)*; U5 4(NC)*; U7 C4(HW_TYP_1/PI5)* D4(HW_TYP_0/PI4)* H1(OSC_OUT/PH1)* R3(T_SW_DIR/PA7)*; U24 4(IO3)*

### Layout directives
differential pair; rule Impedance Constraint [Min = 85.00    Max = 95.00    ]: USB_DEV_HS_CN_N, USB_DEV_HS_CN_P, USB_DEV_HS_N, USB_DEV_HS_P
rule Undefined; rule Matched Net Lengths [Tolerance = 2.5mm]; rule Impedance Constraint [Min = 85.00    Max = 95.00    ]: USB_DEV_HS_N
rule Undefined; rule Matched Net Lengths [Tolerance = 0.2mm]; rule Impedance Constraint [Min = 85.00    Max = 95.00    ]: USB_DEV_HS_CN_N, USB_DEV_HS_CN_P, USB_DEV_HS_P

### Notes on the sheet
- STLINK_MCU
- DFU CONNECTOR
- (near CN2) Connector must be on the border of the PCB
- The routing of the tracks must be done on continuity from ST-LINK to 22ohm resistors and from resistors to Target MCU to avoid stub noises and EMC approach. (22ohm resistors must be very close to STDC14)
- HSE CLK STLINK
- (near R11) level shifter 1V8/3V3
- level shifter 1V8/3V3
- (near JP1) NRST
- STDC14 Receiver
- (near CN5) KEY
- Specific constraints for T_SWDIO and T_SWCLK (must be same length and must be Shielded).
- Pin attributions on ESD can be swapped for layout optimisation
- ST-LINK USB CONNECTOR
- SW LEVEL SHIFTER FOR MCU_1V8
- MCU_1V8/3V3
- ST_LINK_3V3
- (near C6) Capacitor close to pin 1
- (near CN1) STLK
- ST-LINK POWER 3V3 / 150mA

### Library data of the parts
C1 C3 C18 = MCD-00238: as C63 on sheet MCU_144_POWER
C2 C4 = MCD-00211: Capacitor, MLCC, 100nF, 16V, X7R, 10%, 0603, T=0,8mm; Manufacturer_Part_Number: CC0603KRX7R7BB104; Manufacturer: YAGEO; Provided_By: SUBCO; ECCN_US: EAR99; ECCN_EU: NEC
C5 = MCD-00016: Capacitor, MLCC, 20pF, 50V, NPO, 5%, 0402, T=0,5mm; Manufacturer_Part_Number: CC0402JRNPO9BN200; Manufacturer: YAGEO; Provided_By: SUBCO; ECCN_US: EAR99; ECCN_EU: NEC
C6 = MCD-00205: Capacitor, MLCC, 100pF, 50V, NPO, 5%, 0402, T=0,5mm; Manufacturer_Part_Number: CC0402JRNPO9BN101; Manufacturer: YAGEO; Provided_By: SUBCO; ECCN_US: EAR99; ECCN_EU: NEC
C7 C12 C13 = MCD-00012: Capacitor, MLCC, 2.2uF, 10V, X5R, 10%, 0603, T=0,8mm; Manufacturer_Part_Number: CC0603KRX5R6BB225; Manufacturer: YAGEO; Alternate_Manufacturer_Part_Number: C0603C225K8PACTU; Alternate_Manufacturer: KEMET; Provided_By: SUBCO; ECCN_US: EAR99; ECCN_EU: NEC
C8-C11 C14-C17 C20-C22 C24 C25 C28-C34 C37 = MCD-00102: Capacitor, MLCC, 100nF, 16V, X7R, 10%, 0402, T=0,5mm; Manufacturer_Part_Number: CC0402KRX7R7BB104; Manufacturer: YAGEO; Alternate_Manufacturer_Part_Number: GCM155R71C104KA55D; Alternate_Manufacturer: MURATA; Provided_By: SUBCO; ECCN_US: EAR99; ECCN_EU: NEC
C19 = MCD-00011: Capacitor, MLCC, 10nF, 16V, X7R, 10%, 0402, T=0.5mm; Manufacturer_Part_Number: CC0402KRX7R7BB103; Manufacturer: YAGEO; Provided_By: SUBCO; ECCN_US: EAR99; ECCN_EU: NEC
C23 C36 = MCD-00010: Capacitor, MLCC, 1uF, 16V, X5R, 10%, 0603, T=0,8mm; Manufacturer_Part_Number: CC0603KRX5R7BB105; Manufacturer: YAGEO; Provided_By: SUBCO; ECCN_US: EAR99; ECCN_EU: NEC
C26 C27 = MCD-00237: as C79 on sheet Ethernet
C35 = MCD-00009: as C91 on sheet USB
CN1 = MCD-00028: USB-MICRO-B, 0.65mm, RA, SMT, Bottom Mount,; Manufacturer_Part_Number: 1050170001; Manufacturer: MOLEX; Part_Type: Connector; Provided_By: SUBCO
CN2 = MCD-00029: Header, 4x1, 2,54mm, VR, TH, Height 5.84mm/2.54mm; Manufacturer_Part_Number: TSW-104-07-x-S; Manufacturer: SAMTEC; Part_Type: Connector; Provided_By: SUBCO
CN3 CN4 = MCD-00214: Header, 2x1, 2,54mm, VR, TH, Height 5.84mm/10.16mm; Part_Type: Connector; Manufacturer_Part_Number: TSW-102-09-x-S; Manufacturer: SAMTEC; Provided_By: SUBCO
CN5 = MCD-01226: Header 5x2, 1.27mm, Dual row, Straight, Surface mount, vertical male connector. 3.05mm lead. Mates with FFSD connector. Footprint compatible with FTSH-107-01-L-DV,-K,-A,-P,-ES (STDC14 MEDIUM); Manufacturer_Part_Number: FTSH-105-01-L-DV-K; Manufacturer: SAMTEC; Alternate_Manufacturer_Part_Number: P127B-2x05MGF-079-1A; Alternate_Manufacturer: JIUBABA; Provided_By: SUBCO
D1-D3 = MCD-00034: Manufacturer: STMICROELECTRONICS; Part_Type: Diode; BMS_Part_Number: 9151097; Provided_By: SUBCO with ST control; ECCN_US: EAR99; ECCN_EU: NEC
HW6-HW8 = MCD-00043: as HW13 on sheet MCU_144_POWER
JP1 = MCD-00045: Header, 2x1, 2,54mm, VR, TH, Height 5.84mm/2.54mm; Part_Type: Connector; Manufacturer_Part_Number: TSW-102-07-x-S; Manufacturer: SAMTEC; Alternate_Manufacturer_Part_Number: 313102S111116;313102S111116; Alternate_Manufacturer: JIUBABA; LIANYI; Provided_By: SUBCO
JP3 = MCD-00683: Header, 2x1, 2,54mm, VR, TH, Height 5.84mm/2.54mm - Shunt Fitted by default; Part_Type: Connector; Manufacturer_Part_Number: TSW-102-07-x-S; Manufacturer: SAMTEC; Alternate_Manufacturer_Part_Number: 313102S111116; Alternate_Manufacturer: LIANYI; Provided_By: SUBCO
LD4 = MCD-00051: LED Bicolor; Part_Type: Display; Manufacturer_Part_Number: HSMF-A201-A00J1; Manufacturer: AVAGO TECHNOLOGIES; Alternate_Manufacturer_Part_Number: LE-RGW35280; Alternate_Manufacturer: EVERLUCK; Provided_By: SUBCO; ECCN_US: EAR99; ECCN_EU: NEC
LD6 = MCD-00049: LED, Red, 0603; Manufacturer_Part_Number: 19-213-R6C-AP1Q2B/3T; Manufacturer: EVERLIGHT; Part_Type: Display; Provided_By: SUBCO; ECCN_US: EAR99; ECCN_EU: NEC
R1 R4 = MCD-00223: Resistor,100K,0603,1%,1/10W; Manufacturer_Part_Number: RC0603FR-07100KL; Manufacturer: YAGEO; Provided_By: SUBCO; ECCN_US: EAR99; ECCN_EU: NEC
R2 = MCD-00070: Resistor,1K,0603,1%,1/10W; Manufacturer_Part_Number: RC0603FR-071KL; Manufacturer: YAGEO; Provided_By: SUBCO; ECCN_US: EAR99; ECCN_EU: NEC
R3 R10 R11 R13 R23 R29 = MCD-00481: Resistor,47R,0402,1%,1/16W; Manufacturer_Part_Number: RC0402FR-0747RL; Manufacturer: YAGEO; Provided_By: SUBCO; ECCN_US: EAR99; ECCN_EU: NEC
R5 R17 R21 R70 = MCD-00119: Resistor,100R,0402,1%,1/16W; Manufacturer_Part_Number: RC0402FR-07100RL; Manufacturer: YAGEO; Provided_By: SUBCO; ECCN_US: EAR99; ECCN_EU: NEC
R6 = MCD-00185: Resistor,3K,0402,1%,1/16W; Manufacturer_Part_Number: RC0402FR-073KL; Manufacturer: YAGEO; Provided_By: SUBCO; ECCN_US: EAR99; ECCN_EU: NEC
R7 = MCD-00220: Resistor,10K,0603,1%,1/10W; Manufacturer_Part_Number: RC0603FR-0710KL; Manufacturer: YAGEO; Provided_By: SUBCO; ECCN_US: EAR99; ECCN_EU: NEC
R8 R9 = MCD-00197: Resistor,330R,0603,1%,1/10W; Manufacturer_Part_Number: RC0603FR-07330RL; Manufacturer: YAGEO; BMS_Part_Number: 9129729; Provided_By: SUBCO; ECCN_US: EAR99; ECCN_EU: NEC
R14 R18 R20 = MCD-00065: Resistor,4K7,0402,1%,1/16W; Manufacturer_Part_Number: RC0402FR-074K7L; Manufacturer: YAGEO; Alternate_Manufacturer_Part_Number: RT0402FRE074K7L; Provided_By: SUBCO; ECCN_US: EAR99; ECCN_EU: NEC
R15 = MCD-00055: Resistor,2K7,0402,1%,1/16W; Manufacturer_Part_Number: RC0402FR-072K7L; Manufacturer: YAGEO; Provided_By: SUBCO; ECCN_US: EAR99; ECCN_EU: NEC
R22 R24 = MCD-00053: as R66 on sheet USB
SB5 = MCD-00071: as SB18 on sheet MCU_144_POWER
U1 U10 = MCD-00264: Dual bit dual supply bus transceiver; Part_Type: IC; Manufacturer: TEXAS INSTRUMENTS; Provided_By: SUBCO; ECCN_US: EAR99; ECCN_EU: NEC
U2 = MCD-00159: 500mA, Enhanced single channel power switches with active high enable pin; Part_Type: IC; Manufacturer: STMICROELECTRONICS; Alternate_Manufacturer_Part_Number: TPS2051C; Alternate_Manufacturer: TEXAS INSTRUMENTS; BMS_Part_Number: 9159009; Provided_By: SUBCO with ST control; ECCN_US: EAR99; ECCN_EU: NEC
U3 U4 = MCD-00170: as U22 on sheet USB
U5 = MCD-00649: Common mode filter with ESD protection for USB 2.0 interface; Part_Type: Diode; Manufacturer: STMICROELECTRONICS; BMS_Part_Number: 9151138; Provided_By: SUBCO with ST control; ECCN_US: EAR99; ECCN_EU: NEC
U6 = MCD-00251: as U21 on sheet USB
U7 = MCD-00596: STM32F723IEK  (STM32F7) BGA176; Part_Type: IC; Manufacturer_Part_Number: STM32F723IEK6; Manufacturer: STMICROELECTRONICS; BMS_Part_Number: 9175300; Provided_By: SUBCO with ST control; ECCN_US: 3A991A2; ECCN_EU: NEC
U8 U24 = MCD-00136: Dual Transil array for ESD protection; Part_Type: Diode; Manufacturer: STMICROELECTRONICS; BMS_Part_Number: 9151112; Provided_By: SUBCO with ST control; ECCN_US: EAR99; ECCN_EU: NEC
U9 = MCD-00086: Ultra low drop-low noise BiCMOS voltage, regulators low ESR capacitors compatible; Manufacturer: STMICROELECTRONICS; Part_Type: IC; BMS_Part_Number: 9176161; Provided_By: SUBCO with ST control; ECCN_US: EAR99; ECCN_EU: NEC
X1 = MCD-00597: Oscillator 25Mhz, +-50ppm, Vcc:3.3V typ, square wave: [0.1Vcc;0.9Vcc], Enable pin, SMD; Manufacturer_Part_Number: NZ2520SH 25MHz END4869C; Manufacturer: NDK; Alternate_Manufacturer_Part_Number: NZ2520SB 25MHz END4869B; Part_Type: Crystal_Osc; BMS_Part_Number: 9157050; Provided_By: SUBCO; ECCN_US: EAR99; ECCN_EU: NEC

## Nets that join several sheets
1V2_MCU: Connectors (SB95.2), MCU_144_POWER (SB75.2 SB76.2 SB79.1)
1V8_VDD: Power_Board (SB7.2 TP2.1), MCU_144_POWER (JP5.3)
3V3: Connectors (CN8.7 CN11.16 SB24.1), Power_Board (JP4.1 SB1.1 SB2.2 TP1.1), ST_LINK_V3E (CN5.3)
3V3_PER: Connectors (R26.2 R27.2 R28.2 SB13.1), Power_Board (SB1.2), USB (R68.2 R69.2), Ethernet (L2.2), ST_LINK_V3E (R20.2)
3V3_VDD: Connectors (CN6.1 CN11.5), Power_Board (JP4.2 SB6.1), MCU_144_IOs (B1.1 B1.2 R37.2), MCU_144_POWER (JP5.1 SB18.2 SB19.2)
5V: Connectors (CN8.9 CN11.18), Power_Board (8 pins), USB (U18.5), ST_LINK_V3E (R15.1)
5V_EXT: Connectors (CN11.6), Power_Board (JP2.5), ST_LINK_V3E (D2.1)
5V_USB_CHGR: Power_Board (JP2.7), ST_LINK_V3E (8 pins)
5V_USB_STLK: Connectors (CN12.8), Power_Board (JP2.1), ST_LINK_V3E (C1.2 U2.1)
5V_VIN: Power_Board (C41.2 JP2.3 U12.2 U12.4), ST_LINK_V3E (D1.1)
AGND: Connectors (C70.1 CN10.3 CN12.32), MCU_144_POWER (6 pins)
GND: Connectors (31 pins), Power_Board (15 pins), MCU_144_IOs (15 pins), MCU_144_POWER (39 pins), USB (13 pins), Ethernet (22 pins), ST_LINK_V3E (111 pins)
VBAT: Connectors (CN11.33), MCU_144_POWER (C63.2 SB83.2 U14.8)
VDD_MCU: Connectors (SB14.1), MCU_144_POWER (31 pins), USB (R59.2 R64.2), Ethernet (7 pins), ST_LINK_V3E (5 pins)
VDDA: Connectors (CN10.1), MCU_144_POWER (6 pins)
VIN: Connectors (CN8.15 CN11.24), Power_Board (C42.2 U12.3)
VOUTVDD: Connectors (CN6.3), MCU_144_POWER (SB97.1)
VREFP: Connectors (C70.2 SB60.2), MCU_144_POWER (C69.1 C71.2 R39.2 U14.35)
ARD_D0_RX: Connectors (CN10.16), MCU_144_IOs (SB94.2 SB96.1)
ARD_D1_TX: Connectors (CN10.14), MCU_144_IOs (SB11.1 SB15.2)
BOOT0: Connectors (CN11.7), MCU_144_IOs (R36.1 U14.135)
NRST: Connectors (CN8.5 CN11.14), MCU_144_IOs (5 pins), Ethernet (SB98.1)
PA0: Connectors (CN11.28 SB89.1), MCU_144_IOs (SB81.2 U14.37)
PA1: Connectors (CN11.30), MCU_144_IOs (SB80.1 U14.38)
PA2: Connectors (CN12.35 SB78.1), MCU_144_IOs (JP7.2 U14.39)
PA3: Connectors (CN9.1 CN12.37), MCU_144_IOs (U14.40)
PA4: Connectors (CN7.17 CN11.32 SB77.1), MCU_144_IOs (U14.43)
PA5: Connectors (CN7.10 CN12.11 SB65.1), MCU_144_IOs (U14.44)
PA6: Connectors (CN7.12 CN12.13), MCU_144_IOs (U14.45)
PA7: Connectors (CN12.15 SB56.2), MCU_144_IOs (SB52.1 U14.46)
PA8: Connectors (CN12.23 SB28.2), MCU_144_IOs (TP4.1 U14.97)
PA9: Connectors (CN12.21), MCU_144_IOs (SB21.1 U14.98)
PA10: Connectors (CN12.33), MCU_144_IOs (SB29.1 U14.99)
PA11: Connectors (SB22.1), MCU_144_IOs (SB26.1 U14.100)
PA12: Connectors (SB23.1), MCU_144_IOs (SB27.1 U14.101)
PA13: Connectors (CN11.13), MCU_144_IOs (U14.102)
PA14: Connectors (CN11.15), MCU_144_IOs (U14.107)
PA15: Connectors (CN7.9 CN11.17), MCU_144_IOs (U14.108), ST_LINK_V3E (CN5.10 U8.1)
PB0: Connectors (CN10.31 CN11.34 SB54.1), MCU_144_IOs (U14.49)
PB1: Connectors (CN9.7 CN12.24), MCU_144_IOs (U14.50)
PB2: Connectors (CN12.22 SB44.1 SB51.1), MCU_144_IOs (U14.51)
PB3: Connectors (CN12.31 SB49.1), MCU_144_IOs (SB50.2 U14.130)
PB4: Connectors (CN7.19 CN12.27), MCU_144_IOs (U14.131)
PB5: Connectors (SB53.1 SB55.1 SB57.2 SB59.1), MCU_144_IOs (U14.132)
PB6: Connectors (CN12.17), MCU_144_IOs (SB11.2 SB12.2 U14.133)
PB7: Connectors (CN11.21), MCU_144_IOs (SB64.2 SB96.2 U14.134)
PB8: Connectors (CN7.2 CN12.3 SB39.1), MCU_144_IOs (U14.136)
PB9: Connectors (CN7.4 CN12.5 SB62.1), MCU_144_IOs (U14.137)
PB10: Connectors (CN10.32 CN12.25), MCU_144_IOs (U14.66)
PB11: Connectors (CN10.34 CN12.18), MCU_144_IOs (U14.67)
PB12: Connectors (CN7.7 CN12.16), MCU_144_IOs (U14.72)
PB13: Connectors (SB8.1 SB43.1), MCU_144_IOs (JP6.1 U14.73)
PB14: Connectors (CN9.29 R75.1 SB37.1), MCU_144_IOs (U14.74)
PB15: Connectors (CN7.3 CN12.26), MCU_144_IOs (U14.75)
PC0: Connectors (CN9.3 CN11.38), MCU_144_IOs (U14.28)
PC1: Connectors (CN11.36 SB70.1), MCU_144_IOs (SB84.2 U14.29)
PC2: Connectors (CN11.35 SB69.1), MCU_144_IOs (U14.30)
PC3: Connectors (CN9.5 CN11.37), MCU_144_IOs (U14.31)
PC4: Connectors (CN12.34), MCU_144_IOs (SB63.2 U14.47)
PC5: Connectors (CN12.6 SB58.1), MCU_144_IOs (SB48.2 U14.48)
PC6: Connectors (CN7.1 CN12.4), MCU_144_IOs (U14.93)
PC7: Connectors (CN7.11 CN12.19), MCU_144_IOs (U14.94)
PC8: Connectors (CN8.2 SB20.2), MCU_144_IOs (U14.95)
PC9: Connectors (CN8.4 SB9.1), MCU_144_IOs (U14.96)
PC10: Connectors (CN8.6 CN11.1), MCU_144_IOs (U14.109)
PC11: Connectors (CN8.8 CN11.2), MCU_144_IOs (U14.110)
PC12: Connectors (CN8.10 CN11.3), MCU_144_IOs (U14.111)
PC13: Connectors (CN11.23), MCU_144_IOs (SB82.2 U14.9)
PC14: Connectors (SB66.1), MCU_144_IOs (R41.1 U14.10)
PC15: Connectors (SB67.1), MCU_144_IOs (R42.1 U14.11)
PD0: Connectors (CN9.25 CN11.57), MCU_144_IOs (U14.112)
PD1: Connectors (CN9.27 CN11.55), MCU_144_IOs (U14.113)
PD2: Connectors (CN8.12 CN11.4), MCU_144_IOs (U14.114)
PD3: Connectors (CN9.10 CN11.40), MCU_144_IOs (U14.115)
PD4: Connectors (CN9.8 CN11.39), MCU_144_IOs (U14.116)
PD5: Connectors (CN9.6 CN11.41), MCU_144_IOs (U14.117)
PD6: Connectors (CN9.4 CN11.43), MCU_144_IOs (U14.120)
PD7: Connectors (CN9.2 CN11.45), MCU_144_IOs (U14.121)
PD8: Connectors (SB103.2), MCU_144_IOs (SB15.1 SB16.1 U14.76)
PD9: Connectors (SB104.1), MCU_144_IOs (SB17.1 SB94.1 U14.77)
PD10: Connectors (CN12.65 SB99.2), MCU_144_IOs (JP8.2 U14.78)
PD11: Connectors (CN10.23 CN12.45), MCU_144_IOs (U14.81)
PD12: Connectors (CN10.21 CN12.43), MCU_144_IOs (U14.82)
PD13: Connectors (CN10.19 CN12.41), MCU_144_IOs (U14.83)
PD14: Connectors (CN7.16 CN12.46), MCU_144_IOs (U14.84)
PD15: Connectors (CN7.18 CN12.48), MCU_144_IOs (U14.85)
PE0: Connectors (CN10.33 CN12.64), MCU_144_IOs (U14.138)
PE1: Connectors (CN11.61 R74.1), MCU_144_IOs (U14.139)
PE2: Connectors (CN11.46 SB87.1 SB88.2), MCU_144_IOs (U14.1)
PE3: Connectors (CN9.22 CN11.47), MCU_144_IOs (U14.2)
PE4: Connectors (CN9.16 CN11.48), MCU_144_IOs (U14.3)
PE5: Connectors (CN9.18 CN11.50), MCU_144_IOs (U14.4)
PE6: Connectors (CN11.62 SB10.1 SB85.2 SB86.2), MCU_144_IOs (U14.5)
PE7: Connectors (CN10.20 CN12.44), MCU_144_IOs (U14.57)
PE8: Connectors (CN10.18 CN12.40 SB47.1), MCU_144_IOs (U14.58)
PE9: Connectors (CN9.15 CN12.52), MCU_144_IOs (U14.59)
PE10: Connectors (CN10.24 CN12.47), MCU_144_IOs (U14.60)
PE11: Connectors (CN10.6 CN12.56), MCU_144_IOs (U14.61)
PE12: Connectors (CN10.26 CN12.49), MCU_144_IOs (U14.62)
PE13: Connectors (CN10.10 CN12.55), MCU_144_IOs (U14.63)
PE14: Connectors (CN10.8 CN12.51), MCU_144_IOs (U14.64)
PE15: Connectors (CN10.30 CN12.53 SB38.1), MCU_144_IOs (U14.65)
PF6: Connectors (CN11.9 SB73.1), MCU_144_IOs (U14.20)
PF7: Connectors (CN9.26 CN11.11), MCU_144_IOs (U14.21)
PF8: Connectors (CN9.24 CN11.54), MCU_144_IOs (U14.22)
PF9: Connectors (CN9.28 CN11.56), MCU_144_IOs (U14.23)
PF10: Connectors (CN12.42 SB93.1), MCU_144_IOs (SB91.1 U14.24)
PF11: Connectors (CN12.62 SB40.1), MCU_144_IOs (U14.52)
PF14: Connectors (CN9.19 CN12.50), MCU_144_IOs (U14.53)
PF15: Connectors (CN9.21 CN12.60), MCU_144_IOs (U14.54)
PG6: Connectors (CN10.13 CN12.70), MCU_144_IOs (U14.86)
PG7: Connectors (CN12.67), MCU_144_IOs (SB100.2 U14.87)
PG8: Connectors (CN12.66 SB31.2 SB34.2), MCU_144_IOs (U14.88)
PG9: Connectors (CN11.63 SB35.2 SB41.2), MCU_144_IOs (U14.122)
PG10: Connectors (CN11.66 SB30.2 SB33.2), MCU_144_IOs (U14.123)
PG11: Connectors (CN11.70), MCU_144_IOs (SB36.2 U14.124)
PG12: Connectors (CN11.65 SB42.2 SB45.2), MCU_144_IOs (U14.125)
PG13: Connectors (CN11.68), MCU_144_IOs (SB46.2 U14.126)
PG14: Connectors (CN10.12 CN12.61), MCU_144_IOs (U14.127)
PH0: Connectors (SB71.1), MCU_144_IOs (SB3.1 SB72.1 U14.25)
PH1: Connectors (SB90.1), MCU_144_IOs (SB4.1 U14.26)
RMII_CRS_DV: MCU_144_IOs (SB52.2), Ethernet (R44.1)
RMII_MDC: MCU_144_IOs (SB84.1), Ethernet (U15.13)
RMII_MDIO: MCU_144_IOs (JP7.1), Ethernet (R50.1 U15.12)
RMII_REF_CLK: MCU_144_IOs (SB80.2), Ethernet (R52.1)
RMII_RXD0: MCU_144_IOs (SB63.1), Ethernet (R47.1)
RMII_RXD1: MCU_144_IOs (SB48.1), Ethernet (R48.1)
RMII_TX_EN: MCU_144_IOs (SB36.1), Ethernet (U15.16)
RMII_TXD0: MCU_144_IOs (SB46.1), Ethernet (U15.17)
RMII_TXD1: MCU_144_IOs (JP6.2), Ethernet (U15.18)
STLK_MCO: MCU_144_IOs (SB72.2), ST_LINK_V3E (C5.2 R5.2)
T_VCP_RX: MCU_144_IOs (SB17.2 SB64.1), ST_LINK_V3E (CN5.13 R23.2 U24.1)
T_VCP_TX: MCU_144_IOs (SB12.1 SB16.2), ST_LINK_V3E (CN5.14 R3.1 U24.3)
USB_FS_ID: MCU_144_IOs (SB29.2), USB (CN13.4 U22.1)
USB_FS_N: MCU_144_IOs (SB26.2), USB (U19.1)
USB_FS_OVCR: MCU_144_IOs (SB100.1), USB (LD7.2 R64.1 U18.3)
USB_FS_P: MCU_144_IOs (SB27.2), USB (U19.3)
USB_FS_PWR_EN: MCU_144_IOs (JP8.1 SB91.2), USB (R59.1 U18.4)
USB_FS_VBUS: MCU_144_IOs (R63.1), USB (5 pins)

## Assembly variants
H745ZIQ: not fitted C61 C62 C74 C76 C77 C78 CN2 CN6 CN11 CN12 R33 R34 R38 R57 R58 R70 SB3 SB4 SB5 SB8 SB9 SB10 SB12 SB13 SB15 SB20 SB22 SB23 SB24 SB25 SB38 SB39 SB44 SB47 SB55 SB56 SB58 SB62 SB64 SB65 SB66 SB67 SB70 SB71 SB74 SB77 SB78 SB81 SB90 SB91 SB94 SB95 SB97 SB99 SB101 SB102 X2
H755ZIQ: not fitted C61 C62 C74 C76 C77 C78 CN2 CN6 CN11 CN12 R33 R34 R38 R57 R58 R70 SB3 SB4 SB5 SB8 SB9 SB10 SB12 SB13 SB15 SB20 SB22 SB23 SB24 SB25 SB38 SB39 SB44 SB47 SB55 SB56 SB58 SB62 SB64 SB65 SB66 SB67 SB70 SB71 SB74 SB77 SB78 SB81 SB90 SB91 SB94 SB95 SB97 SB99 SB101 SB102 X2
H7A3ZIQ: not fitted C61 C62 C74 C76 C77 C78 C79 C80 C81 C82 C83 C84 C85 C86 C87 C88 C89 C90 CN2 CN6 CN11 CN12 CN14 HW3 HW14 HW15 JP6 JP7 JP8 L2 R33 R34 R38 R43 R44 R45 R46 R47 R48 R49 R50 R51 R52 R53 R54 R55 R56 R57 R58 R60 R61 R62 R70 R78 R79 R80 R81 SB3 SB4 SB5 SB9 SB10 SB12 SB13 SB15 SB20 SB22 SB23 SB24 SB25 SB36 SB38 SB39 SB44 SB46 SB47 SB48 SB52 SB55 SB57 SB62 SB63 SB64 SB65 SB66 SB67 SB71 SB73 SB74 SB77 SB80 SB81 SB84 SB90 SB93 SB94 SB95 SB97 SB98 SB101 SB102 U15 U16 U17 X2 X4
